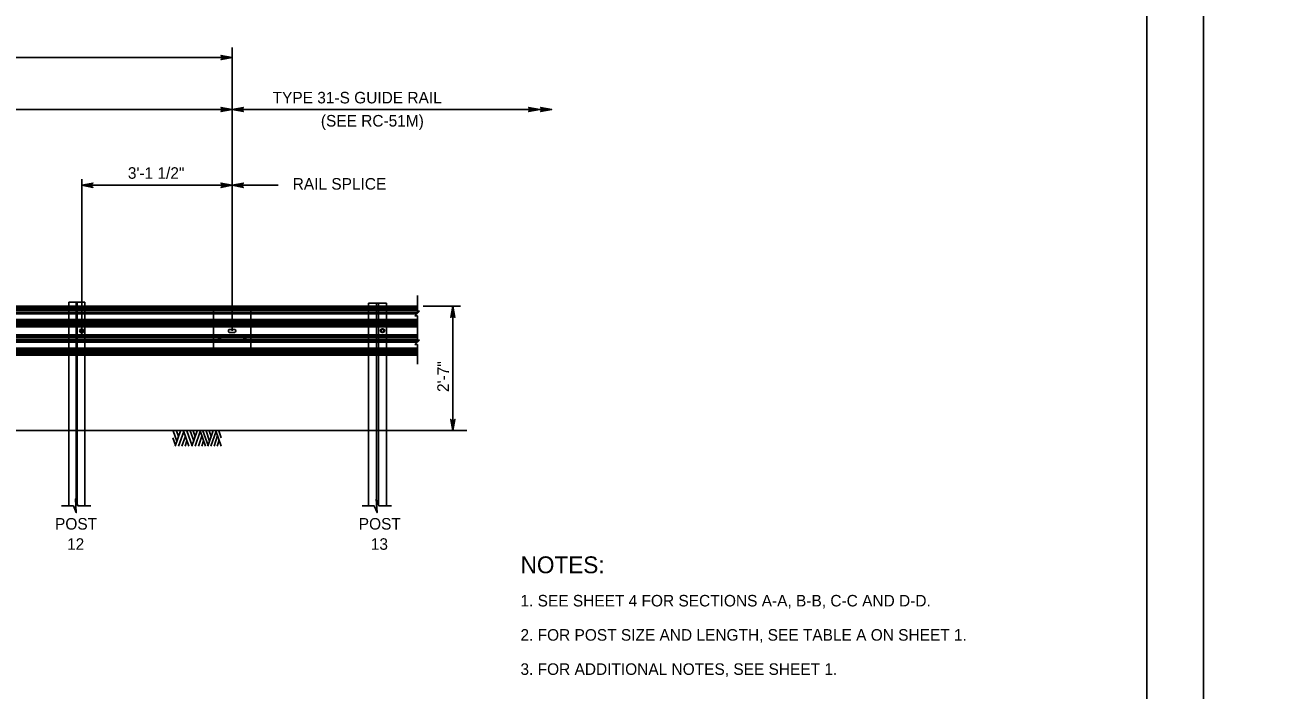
# Model space of a CAD drawing. Extents: x 632007860 to 635435983, y 295418622 to 297794622.
# Drawn here: x 632537853 to 632865880, y 296768980 to 296944470 of the extents above; entities that cross this region are included whole.
import ezdxf

# ---------------------------------------------------------------- set-up
doc = ezdxf.new("R2010")
doc.units = 0
for name, color, linetype in [('1', 7, 'Continuous'), ('PLT-BNDY', 7, 'Continuous'), ('S-DETL-DIMS', 7, 'Continuous'), ('S-DETL-T120', 7, 'Continuous'), ('S-DETL-T175', 7, 'Continuous'), ('S-GRND-MAJR', 7, 'Continuous'), ('S-MISC-CNTR-WT01', 7, 'Continuous'), ('S-STEL', 7, 'Continuous')]:
    doc.layers.add(name, color=color, linetype=linetype)

msp = doc.modelspace()

# ---------------------------------------------------------------- linework, layer by layer
at = {"layer": '1'}
msp.add_lwpolyline([(632833860, 296621622), (632833860, 297185622), (632047860, 297185622), (632047860, 296621622), (632833860, 296621622), (632833860, 296647981), (632633860, 296647981), (632633860, 296712659), (632833860, 296712659), (632833860, 296741622), (632633860, 296741622), (632633860, 296621622), (632712661, 296621622), (632712661, 296647981), (632712661, 296621622), (632789661, 296621622), (632789661, 296647981), (632789661, 296635665), (632833860, 296635665)], dxfattribs=at)
at = {"layer": 'PLT-BNDY'}
for points in [[(632007860, 297200622), (632848860, 297200622), (632848860, 296606622), (632007860, 296606622)], [(632848860, 297200622), (633689860, 297200622), (633689860, 296606622), (632848860, 296606622)]]:
    msp.add_lwpolyline(points, close=True, dxfattribs=at)
at = {"layer": 'S-DETL-DIMS'}
for p, q in [((632101688, 296935848), (632592545, 296935848)), ((632147770, 296922136), (632589965, 296922136)), ((632592545, 296922136), (632676869, 296922136)), ((632552857, 296902162), (632604725, 296902162)), ((632592545, 296902162), (632604725, 296902162)), ((632641431, 296873064), (632641431, 296868962)), ((632641948, 296868962), (632640785, 296867677)), ((632641431, 296868962), (632641948, 296868962)), ((632642934, 296870247), (632652784, 296870247)), ((632650765, 296870247), (632650765, 296837438)), ((632640785, 296867677), (632641431, 296867677)), ((632641431, 296867677), (632641431, 296865279)), ((632641431, 296865279), (632641431, 296861338)), ((632641948, 296861338), (632640785, 296860139)), ((632641431, 296861338), (632641948, 296861338)), ((632640785, 296860139), (632641431, 296860139)), ((632641431, 296860139), (632641431, 296854972)), ((632550679, 296817603), (632547504, 296817603)), ((632555251, 296817603), (632551870, 296817603)), ((632630054, 296817603), (632626879, 296817603)), ((632634627, 296817603), (632631245, 296817603))]:
    msp.add_line(p, q, dxfattribs=at)
for points in [[(632592545, 296935848), (632589586, 296935293), (632589700, 296935372), (632589814, 296935451), (632589873, 296935551), (632589931, 296935650), (632589948, 296935749), (632589965, 296935848), (632589948, 296935947), (632589931, 296936047), (632589873, 296936146), (632589814, 296936245), (632589700, 296936324), (632589586, 296936403), (632592545, 296935848), (632589700, 296936324), (632589814, 296936245), (632592545, 296935848), (632589873, 296936146), (632589931, 296936047), (632592545, 296935848), (632589948, 296935947), (632589965, 296935848), (632592545, 296935848), (632589948, 296935749), (632589931, 296935650), (632592545, 296935848), (632589873, 296935551), (632589814, 296935451), (632592545, 296935848), (632589700, 296935372)], [(632592545, 296922136), (632589586, 296921581), (632589814, 296921739), (632589931, 296921938), (632589965, 296922136), (632589931, 296922335), (632589814, 296922533), (632589586, 296922691), (632592545, 296922136), (632589814, 296922533), (632589931, 296922335), (632592545, 296922136), (632589965, 296922136), (632589931, 296921938), (632592545, 296922136), (632589814, 296921739)], [(632592545, 296922136), (632595504, 296922691), (632595276, 296922533), (632595159, 296922335), (632595125, 296922136), (632595159, 296921938), (632595276, 296921739), (632595504, 296921581), (632592545, 296922136), (632595276, 296921739), (632595159, 296921938), (632592545, 296922136), (632595125, 296922136), (632595159, 296922335), (632592545, 296922136), (632595276, 296922533)], [(632673720, 296922136), (632670760, 296921581), (632670989, 296921739), (632671106, 296921938), (632671140, 296922136), (632671106, 296922335), (632670989, 296922533), (632670760, 296922691), (632673720, 296922136), (632670989, 296922533), (632671106, 296922335), (632673720, 296922136), (632671140, 296922136), (632671106, 296921938), (632673720, 296922136), (632670989, 296921739)], [(632676869, 296922136), (632673910, 296921581), (632674138, 296921739), (632674256, 296921938), (632674290, 296922136), (632674256, 296922335), (632674138, 296922533), (632673910, 296922691), (632676869, 296922136), (632674138, 296922533), (632674256, 296922335), (632676869, 296922136), (632674290, 296922136), (632674256, 296921938), (632676869, 296922136), (632674138, 296921739)], [(632552857, 296902162), (632555817, 296902716), (632555703, 296902637), (632555589, 296902558), (632555530, 296902459), (632555471, 296902360), (632555454, 296902261), (632555437, 296902162), (632555454, 296902062), (632555471, 296901963), (632555530, 296901864), (632555589, 296901765), (632555703, 296901686), (632555817, 296901607), (632552857, 296902162), (632555703, 296901686), (632555589, 296901765), (632552857, 296902162), (632555530, 296901864), (632555471, 296901963), (632552857, 296902162), (632555454, 296902062), (632555437, 296902162), (632552857, 296902162), (632555454, 296902261), (632555471, 296902360), (632552857, 296902162), (632555530, 296902459), (632555589, 296902558), (632552857, 296902162), (632555703, 296902637)], [(632592545, 296902162), (632589586, 296902716), (632589700, 296902637), (632589814, 296902558), (632589873, 296902459), (632589931, 296902360), (632589948, 296902261), (632589965, 296902162), (632589948, 296902062), (632589931, 296901963), (632589873, 296901864), (632589814, 296901765), (632589700, 296901686), (632589586, 296901607), (632592545, 296902162), (632589700, 296901686), (632589814, 296901765), (632592545, 296902162), (632589873, 296901864), (632589931, 296901963), (632592545, 296902162), (632589948, 296902062), (632589965, 296902162), (632592545, 296902162), (632589948, 296902261), (632589931, 296902360), (632592545, 296902162), (632589873, 296902459), (632589814, 296902558), (632592545, 296902162), (632589700, 296902637)], [(632592545, 296902162), (632595504, 296902716), (632595390, 296902637), (632595276, 296902558), (632595218, 296902459), (632595159, 296902360), (632595142, 296902261), (632595125, 296902162), (632595142, 296902062), (632595159, 296901963), (632595218, 296901864), (632595276, 296901765), (632595390, 296901686), (632595504, 296901607), (632592545, 296902162), (632595390, 296901686), (632595276, 296901765), (632592545, 296902162), (632595218, 296901864), (632595159, 296901963), (632592545, 296902162), (632595142, 296902062), (632595125, 296902162), (632592545, 296902162), (632595142, 296902261), (632595159, 296902360), (632592545, 296902162), (632595218, 296902459), (632595276, 296902558), (632592545, 296902162), (632595390, 296902637)], [(632650765, 296870247), (632650210, 296867288), (632650289, 296867402), (632650368, 296867516), (632650467, 296867575), (632650566, 296867633), (632650666, 296867650), (632650765, 296867667), (632650864, 296867650), (632650963, 296867633), (632651062, 296867575), (632651162, 296867516), (632651241, 296867402), (632651320, 296867288), (632650765, 296870247), (632651241, 296867402), (632651162, 296867516), (632650765, 296870247), (632651062, 296867575), (632650963, 296867633), (632650765, 296870247), (632650864, 296867650), (632650765, 296867667), (632650765, 296870247), (632650666, 296867650), (632650566, 296867633), (632650765, 296870247), (632650467, 296867575), (632650368, 296867516), (632650765, 296870247), (632650289, 296867402)], [(632650765, 296837438), (632651320, 296840398), (632651241, 296840284), (632651162, 296840170), (632651062, 296840111), (632650963, 296840052), (632650864, 296840035), (632650765, 296840018), (632650666, 296840035), (632650566, 296840052), (632650467, 296840111), (632650368, 296840170), (632650289, 296840284), (632650210, 296840398), (632650765, 296837438), (632650289, 296840284), (632650368, 296840170), (632650765, 296837438), (632650467, 296840111), (632650566, 296840052), (632650765, 296837438), (632650666, 296840035), (632650765, 296840018), (632650765, 296837438), (632650864, 296840035), (632650963, 296840052), (632650765, 296837438), (632651062, 296840111), (632651162, 296840170), (632650765, 296837438), (632651241, 296840284)], [(632550679, 296817603), (632551404, 296815817), (632551188, 296819389), (632551870, 296817603)], [(632630054, 296817603), (632630779, 296815817), (632630563, 296819389), (632631245, 296817603)]]:
    msp.add_lwpolyline(points, dxfattribs=at)
at = {"layer": 'S-GRND-MAJR'}
for p, q in [((632101688, 296837439), (632654453, 296837439)), ((632577569, 296833603), (632576892, 296835525)), ((632577950, 296834690), (632576987, 296837421)), ((632577483, 296833350), (632578904, 296837421)), ((632578360, 296835866), (632577826, 296837421)), ((632578399, 296833350), (632579762, 296837232)), ((632579276, 296833350), (632580201, 296835992)), ((632581126, 296833350), (632579696, 296837421)), ((632581966, 296833464), (632580583, 296837421)), ((632582405, 296834728), (632581470, 296837421)), ((632581928, 296833350), (632583349, 296837421)), ((632582805, 296835916), (632582290, 296837421)), ((632582777, 296833350), (632584131, 296837219)), ((632583654, 296833350), (632584570, 296835992)), ((632585504, 296833350), (632584064, 296837421)), ((632586201, 296833476), (632584818, 296837421)), ((632586611, 296834652), (632585648, 296837421)), ((632586153, 296833350), (632587574, 296837434)), ((632587040, 296835879), (632586506, 296837421)), ((632586916, 296833350), (632588290, 296837295)), ((632587755, 296833350), (632588709, 296836119)), ((632589682, 296833350), (632588261, 296837421)), ((632588566, 296833350), (632589119, 296834956)), ((632589682, 296835525), (632589024, 296837421)), ((632576982, 296833350), (632576982, 296833350)), ((632580144, 296833350), (632580630, 296834753)), ((632584551, 296833350), (632585018, 296834715))]:
    msp.add_line(p, q, dxfattribs=at)
at = {"layer": 'S-MISC-CNTR-WT01'}
for p, q in [((632592545, 296863765), (632592545, 296938530)), ((632552857, 296862455), (632552857, 296903762))]:
    msp.add_line(p, q, dxfattribs=at)
at = {"layer": 'S-STEL'}
for p, q in [((632549413, 296871305), (632553647, 296871305)), ((632549413, 296871305), (632549413, 296870246)), ((632551398, 296871018), (632551398, 296818753)), ((632551662, 296871018), (632551662, 296818234)), ((632553647, 296871305), (632553647, 296870246)), ((632628514, 296871018), (632633296, 296871018)), ((632628514, 296871018), (632628579, 296871018)), ((632628514, 296871018), (632628579, 296871018)), ((632628514, 296871018), (632628579, 296871018)), ((632628514, 296871018), (632628579, 296871018)), ((632628514, 296871018), (632628514, 296870247)), ((632630647, 296817603), (632630647, 296871018)), ((632631164, 296817603), (632631164, 296871018)), ((632633296, 296871018), (632633296, 296870247)), ((632641431, 296869647), (632428175, 296869647)), ((632641431, 296870247), (632428202, 296870247)), ((632641431, 296870076), (632428202, 296870076)), ((632641431, 296869647), (632428202, 296869647)), ((632641431, 296869219), (632428202, 296869219)), ((632641715, 296868705), (632428202, 296868705)), ((632641328, 296868277), (632428202, 296868277)), ((632549413, 296870246), (632549413, 296857312)), ((632553647, 296870246), (632553647, 296857312)), ((632587616, 296870247), (632587616, 296857312)), ((632589095, 296869819), (632589292, 296869819)), ((632589095, 296869728), (632589095, 296869819)), ((632589292, 296869728), (632589095, 296869728)), ((632589095, 296869233), (632589292, 296869233)), ((632589292, 296869728), (632589292, 296869819)), ((632595800, 296869819), (632595997, 296869819)), ((632595800, 296869728), (632595800, 296869819)), ((632595997, 296869728), (632595800, 296869728)), ((632595800, 296869233), (632595997, 296869233)), ((632595997, 296869728), (632595997, 296869819)), ((632597476, 296870247), (632597476, 296857312)), ((632628514, 296857312), (632628514, 296870247)), ((632633296, 296857312), (632633296, 296870247)), ((632641431, 296866735), (632428202, 296866735)), ((632641431, 296866307), (632428202, 296866307)), ((632641431, 296865878), (632428202, 296865878)), ((632641431, 296865450), (632428202, 296865450)), ((632641431, 296865022), (632428202, 296865022)), ((632641431, 296864850), (632428202, 296864850)), ((632589095, 296866223), (632589292, 296866223)), ((632589095, 296865728), (632589095, 296865637)), ((632589292, 296865728), (632589095, 296865728)), ((632589095, 296865637), (632589292, 296865637)), ((632589292, 296865728), (632589292, 296865637)), ((632595800, 296866223), (632595997, 296866223)), ((632595800, 296865728), (632595800, 296865637)), ((632595997, 296865728), (632595800, 296865728)), ((632595800, 296865637), (632595997, 296865637)), ((632595997, 296865728), (632595997, 296865637)), ((632641431, 296862709), (632428202, 296862709)), ((632641431, 296862538), (632428202, 296862538)), ((632641431, 296862109), (632428202, 296862109)), ((632641431, 296861595), (632428202, 296861595)), ((632641782, 296861167), (632428202, 296861167)), ((632552266, 296863751), (632552266, 296863742)), ((632552976, 296864224), (632552739, 296864224)), ((632552739, 296863269), (632552976, 296863269)), ((632553449, 296863742), (632553449, 296863751)), ((632589095, 296861832), (632589292, 296861832)), ((632589095, 296861741), (632589095, 296861832)), ((632589292, 296861741), (632589095, 296861741)), ((632589095, 296861247), (632589292, 296861247)), ((632589292, 296861741), (632589292, 296861832)), ((632593236, 296864127), (632591856, 296864127)), ((632591856, 296863343), (632593236, 296863343)), ((632595800, 296861832), (632595997, 296861832)), ((632595800, 296861741), (632595800, 296861832)), ((632595997, 296861741), (632595800, 296861741)), ((632595800, 296861247), (632595997, 296861247)), ((632595997, 296861741), (632595997, 296861832)), ((632631610, 296863811), (632631610, 296863819)), ((632631610, 296863811), (632631610, 296863819)), ((632632083, 296864292), (632632320, 296864292)), ((632632083, 296864292), (632632320, 296864292)), ((632632320, 296863338), (632632083, 296863338)), ((632632320, 296863338), (632632083, 296863338)), ((632632793, 296863819), (632632793, 296863811)), ((632632793, 296863819), (632632793, 296863811)), ((632641366, 296860739), (632428202, 296860739)), ((632641431, 296859197), (632428202, 296859197)), ((632641431, 296858768), (632428202, 296858768)), ((632641431, 296858340), (632428202, 296858340)), ((632641431, 296857912), (632428202, 296857912)), ((632589095, 296858236), (632589292, 296858236)), ((632595800, 296858236), (632595997, 296858236)), ((632641431, 296857484), (632428202, 296857484)), ((632641431, 296857312), (632428202, 296857312)), ((632549413, 296857312), (632549413, 296837438)), ((632553647, 296857312), (632553647, 296837438)), ((632589095, 296857742), (632589095, 296857651)), ((632589292, 296857742), (632589095, 296857742)), ((632589095, 296857651), (632589292, 296857651)), ((632589292, 296857742), (632589292, 296857651)), ((632595800, 296857742), (632595800, 296857651)), ((632595997, 296857742), (632595800, 296857742)), ((632595800, 296857651), (632595997, 296857651)), ((632595997, 296857742), (632595997, 296857651)), ((632628514, 296857312), (632628514, 296837439)), ((632633296, 296837439), (632633296, 296857312)), ((632549413, 296837438), (632549413, 296817602)), ((632553647, 296837438), (632553647, 296817602)), ((632628514, 296817603), (632628514, 296837439)), ((632633296, 296817603), (632633296, 296837439))]:
    msp.add_line(p, q, dxfattribs=at)
for points in [[(632589095, 296869233), (632589027, 296869238), (632588960, 296869251), (632588898, 296869273), (632588842, 296869302), (632588793, 296869338), (632588754, 296869380), (632588725, 296869426), (632588707, 296869475), (632588701, 296869526), (632588707, 296869577), (632588725, 296869626), (632588754, 296869672), (632588793, 296869714), (632588842, 296869750), (632588898, 296869780), (632588960, 296869801), (632589027, 296869814), (632589095, 296869819)], [(632589095, 296869728), (632589027, 296869723), (632588960, 296869710), (632588898, 296869689), (632588842, 296869659), (632588793, 296869623), (632588754, 296869581), (632588725, 296869535), (632588707, 296869486), (632588706, 296869481)], [(632589292, 296869819), (632589361, 296869814), (632589427, 296869801), (632589490, 296869780), (632589546, 296869750), (632589594, 296869714), (632589634, 296869672), (632589663, 296869626), (632589681, 296869577), (632589687, 296869526), (632589681, 296869475), (632589663, 296869426), (632589634, 296869380), (632589594, 296869338), (632589546, 296869302), (632589490, 296869273), (632589427, 296869251), (632589361, 296869238), (632589292, 296869233)], [(632589682, 296869481), (632589681, 296869486), (632589663, 296869535), (632589634, 296869581), (632589594, 296869623), (632589546, 296869659), (632589490, 296869689), (632589427, 296869710), (632589361, 296869723), (632589292, 296869728)], [(632595800, 296869233), (632595731, 296869238), (632595665, 296869251), (632595603, 296869273), (632595546, 296869302), (632595498, 296869338), (632595458, 296869380), (632595429, 296869426), (632595411, 296869475), (632595405, 296869526), (632595411, 296869577), (632595429, 296869626), (632595458, 296869672), (632595498, 296869714), (632595546, 296869750), (632595603, 296869780), (632595665, 296869801), (632595731, 296869814), (632595800, 296869819)], [(632595800, 296869728), (632595731, 296869723), (632595665, 296869710), (632595603, 296869689), (632595546, 296869659), (632595498, 296869623), (632595458, 296869581), (632595429, 296869535), (632595411, 296869486), (632595410, 296869481)], [(632595997, 296869819), (632596065, 296869814), (632596132, 296869801), (632596194, 296869780), (632596250, 296869750), (632596299, 296869714), (632596338, 296869672), (632596368, 296869626), (632596385, 296869577), (632596391, 296869526), (632596385, 296869475), (632596368, 296869426), (632596338, 296869380), (632596299, 296869338), (632596250, 296869302), (632596194, 296869273), (632596132, 296869251), (632596065, 296869238), (632595997, 296869233)], [(632596387, 296869481), (632596385, 296869486), (632596368, 296869535), (632596338, 296869581), (632596299, 296869623), (632596250, 296869659), (632596194, 296869689), (632596132, 296869710), (632596065, 296869723), (632595997, 296869728)], [(632589095, 296866223), (632589027, 296866218), (632588960, 296866205), (632588898, 296866184), (632588842, 296866154), (632588793, 296866118), (632588754, 296866076), (632588725, 296866030), (632588707, 296865981), (632588701, 296865930), (632588707, 296865879), (632588725, 296865830), (632588754, 296865784), (632588793, 296865742), (632588842, 296865706), (632588898, 296865677), (632588960, 296865655), (632589027, 296865642), (632589095, 296865637)], [(632589095, 296865728), (632589027, 296865733), (632588960, 296865746), (632588898, 296865768), (632588842, 296865797), (632588793, 296865833), (632588754, 296865875), (632588725, 296865921), (632588707, 296865970), (632588706, 296865976)], [(632589292, 296865637), (632589361, 296865642), (632589427, 296865655), (632589490, 296865677), (632589546, 296865706), (632589594, 296865742), (632589634, 296865784), (632589663, 296865830), (632589681, 296865879), (632589687, 296865930), (632589681, 296865981), (632589663, 296866030), (632589634, 296866076), (632589594, 296866118), (632589546, 296866154), (632589490, 296866184), (632589427, 296866205), (632589361, 296866218), (632589292, 296866223)], [(632589682, 296865976), (632589681, 296865970), (632589663, 296865921), (632589634, 296865875), (632589594, 296865833), (632589546, 296865797), (632589490, 296865768), (632589427, 296865746), (632589361, 296865733), (632589292, 296865728)], [(632595800, 296866223), (632595731, 296866218), (632595665, 296866205), (632595603, 296866184), (632595546, 296866154), (632595498, 296866118), (632595458, 296866076), (632595429, 296866030), (632595411, 296865981), (632595405, 296865930), (632595411, 296865879), (632595429, 296865830), (632595458, 296865784), (632595498, 296865742), (632595546, 296865706), (632595603, 296865677), (632595665, 296865655), (632595731, 296865642), (632595800, 296865637)], [(632595800, 296865728), (632595731, 296865733), (632595665, 296865746), (632595603, 296865768), (632595546, 296865797), (632595498, 296865833), (632595458, 296865875), (632595429, 296865921), (632595411, 296865970), (632595410, 296865976)], [(632595997, 296865637), (632596065, 296865642), (632596132, 296865655), (632596194, 296865677), (632596250, 296865706), (632596299, 296865742), (632596338, 296865784), (632596368, 296865830), (632596385, 296865879), (632596391, 296865930), (632596385, 296865981), (632596368, 296866030), (632596338, 296866076), (632596299, 296866118), (632596250, 296866154), (632596194, 296866184), (632596132, 296866205), (632596065, 296866218), (632595997, 296866223)], [(632596387, 296865976), (632596385, 296865970), (632596368, 296865921), (632596338, 296865875), (632596299, 296865833), (632596250, 296865797), (632596194, 296865768), (632596132, 296865746), (632596065, 296865733), (632595997, 296865728)], [(632589095, 296861247), (632589027, 296861251), (632588960, 296861265), (632588898, 296861286), (632588842, 296861315), (632588793, 296861352), (632588754, 296861393), (632588725, 296861440), (632588707, 296861489), (632588701, 296861540), (632588707, 296861590), (632588725, 296861640), (632588754, 296861686), (632588793, 296861728), (632588842, 296861764), (632588898, 296861793), (632588960, 296861815), (632589027, 296861828), (632589095, 296861832)], [(632589095, 296861741), (632589027, 296861737), (632588960, 296861724), (632588898, 296861702), (632588842, 296861673), (632588793, 296861637), (632588754, 296861595), (632588725, 296861549), (632588707, 296861499), (632588706, 296861494)], [(632589292, 296861832), (632589361, 296861828), (632589427, 296861815), (632589490, 296861793), (632589546, 296861764), (632589594, 296861728), (632589634, 296861686), (632589663, 296861640), (632589681, 296861590), (632589687, 296861540), (632589681, 296861489), (632589663, 296861440), (632589634, 296861393), (632589594, 296861352), (632589546, 296861315), (632589490, 296861286), (632589427, 296861265), (632589361, 296861251), (632589292, 296861247)], [(632589682, 296861494), (632589681, 296861499), (632589663, 296861549), (632589634, 296861595), (632589594, 296861637), (632589546, 296861673), (632589490, 296861702), (632589427, 296861724), (632589361, 296861737), (632589292, 296861741)], [(632595800, 296861247), (632595731, 296861251), (632595665, 296861265), (632595603, 296861286), (632595546, 296861315), (632595498, 296861352), (632595458, 296861393), (632595429, 296861440), (632595411, 296861489), (632595405, 296861540), (632595411, 296861590), (632595429, 296861640), (632595458, 296861686), (632595498, 296861728), (632595546, 296861764), (632595603, 296861793), (632595665, 296861815), (632595731, 296861828), (632595800, 296861832)], [(632595800, 296861741), (632595731, 296861737), (632595665, 296861724), (632595603, 296861702), (632595546, 296861673), (632595498, 296861637), (632595458, 296861595), (632595429, 296861549), (632595411, 296861499), (632595410, 296861494)], [(632595997, 296861832), (632596065, 296861828), (632596132, 296861815), (632596194, 296861793), (632596250, 296861764), (632596299, 296861728), (632596338, 296861686), (632596368, 296861640), (632596385, 296861590), (632596391, 296861540), (632596385, 296861489), (632596368, 296861440), (632596338, 296861393), (632596299, 296861352), (632596250, 296861315), (632596194, 296861286), (632596132, 296861265), (632596065, 296861251), (632595997, 296861247)], [(632596387, 296861494), (632596385, 296861499), (632596368, 296861549), (632596338, 296861595), (632596299, 296861637), (632596250, 296861673), (632596194, 296861702), (632596132, 296861724), (632596065, 296861737), (632595997, 296861741)], [(632589095, 296858236), (632589027, 296858232), (632588960, 296858219), (632588898, 296858197), (632588842, 296858168), (632588793, 296858132), (632588754, 296858090), (632588725, 296858044), (632588707, 296857995), (632588701, 296857944), (632588707, 296857893), (632588725, 296857844), (632588754, 296857797), (632588793, 296857756), (632588842, 296857719), (632588898, 296857690), (632588960, 296857669), (632589027, 296857655), (632589095, 296857651)], [(632589095, 296857742), (632589027, 296857746), (632588960, 296857760), (632588898, 296857781), (632588842, 296857811), (632588793, 296857847), (632588754, 296857888), (632588725, 296857935), (632588707, 296857984), (632588706, 296857989)], [(632589292, 296857651), (632589361, 296857655), (632589427, 296857669), (632589490, 296857690), (632589546, 296857719), (632589594, 296857756), (632589634, 296857797), (632589663, 296857844), (632589681, 296857893), (632589687, 296857944), (632589681, 296857995), (632589663, 296858044), (632589634, 296858090), (632589594, 296858132), (632589546, 296858168), (632589490, 296858197), (632589427, 296858219), (632589361, 296858232), (632589292, 296858236)], [(632589682, 296857989), (632589681, 296857984), (632589663, 296857935), (632589634, 296857888), (632589594, 296857847), (632589546, 296857811), (632589490, 296857781), (632589427, 296857760), (632589361, 296857746), (632589292, 296857742)], [(632595800, 296858236), (632595731, 296858232), (632595665, 296858219), (632595603, 296858197), (632595546, 296858168), (632595498, 296858132), (632595458, 296858090), (632595429, 296858044), (632595411, 296857995), (632595405, 296857944), (632595411, 296857893), (632595429, 296857844), (632595458, 296857797), (632595498, 296857756), (632595546, 296857719), (632595603, 296857690), (632595665, 296857669), (632595731, 296857655), (632595800, 296857651)], [(632595800, 296857742), (632595731, 296857746), (632595665, 296857760), (632595603, 296857781), (632595546, 296857811), (632595498, 296857847), (632595458, 296857888), (632595429, 296857935), (632595411, 296857984), (632595410, 296857989)], [(632595997, 296857651), (632596065, 296857655), (632596132, 296857669), (632596194, 296857690), (632596250, 296857719), (632596299, 296857756), (632596338, 296857797), (632596368, 296857844), (632596385, 296857893), (632596391, 296857944), (632596385, 296857995), (632596368, 296858044), (632596338, 296858090), (632596299, 296858132), (632596250, 296858168), (632596194, 296858197), (632596132, 296858219), (632596065, 296858232), (632595997, 296858236)], [(632596387, 296857989), (632596385, 296857984), (632596368, 296857935), (632596338, 296857888), (632596299, 296857847), (632596250, 296857811), (632596194, 296857781), (632596132, 296857760), (632596065, 296857746), (632595997, 296857742)]]:
    msp.add_lwpolyline(points, dxfattribs=at)
for centre in [(632552857, 296863764), (632632202, 296863764)]:
    msp.add_circle(centre, 397, dxfattribs=at)
for centre, start, end in [((632552739, 296863751), 90, 180), ((632552739, 296863742), 180, 270), ((632552976, 296863751), 0, 90), ((632552976, 296863742), 270, 360), ((632632083, 296863819), 90, 180), ((632632083, 296863819), 90, 180), ((632632083, 296863811), 180, 270), ((632632083, 296863811), 180, 270), ((632632320, 296863819), 0, 90), ((632632320, 296863819), 0, 90), ((632632320, 296863811), 270, 0), ((632632320, 296863811), 270, 0)]:
    msp.add_arc(centre, 473, start, end, dxfattribs=at)
for centre, start_param, end_param in [((632591856, 296863735), 6.2831853, 9.424778), ((632593236, 296863735), 3.1415927, 6.2831853)]:
    msp.add_ellipse(centre, major_axis=(0, 392), ratio=0.7543445, start_param=start_param, end_param=end_param, dxfattribs=at)

# ---------------------------------------------------------------- texts
at = {"layer": 'S-DETL-T120'}
for s, height, p in [('TYPE 31-S GUIDE RAIL', 3048.01, (632603225, 296923751)), ('(SEE RC-51M)', 3048.01, (632615945, 296917655)), ('3\'-1 1/2"', 3048, (632565031, 296903868)), ('  RAIL SPLICE', 3048.01, (632606251, 296901005)), ('POST', 3048, (632545814, 296811326)), ('POST', 3048, (632625954, 296811326)), ('12', 3048, (632548982, 296805992)), ('13', 3048, (632629122, 296805992))]:
    msp.add_text(s, height=height, dxfattribs=at).set_placement(p)
for s, height, rotation, p in [('2\'-7"', 3048.1, 90, (632649716, 296847628)), ('1. SEE SHEET 4 FOR SECTIONS A-A, B-B, C-C AND D-D.', 3048.06, 360, (632668614, 296791049)), ('2. FOR POST SIZE AND LENGTH, SEE TABLE A ON SHEET 1.', 3048.06, 360, (632668614, 296782024)), ('3. FOR ADDITIONAL NOTES, SEE SHEET 1.', 3048.06, 360, (632668614, 296773000))]:
    msp.add_text(s, height=height, rotation=rotation, dxfattribs=at).set_placement(p)
at = {"layer": 'S-DETL-T175'}
msp.add_text('NOTES:', height=4450, dxfattribs=at).set_placement((632668656, 296799813))

doc.saveas('drawing.dxf')
